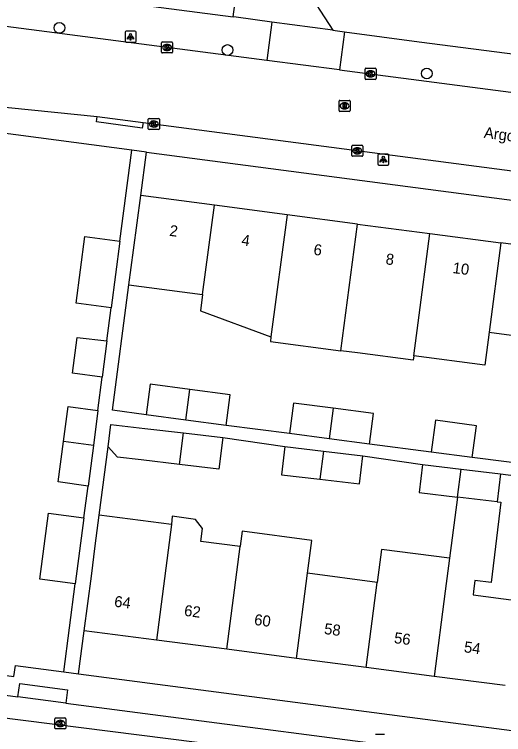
# Model space of a CAD drawing. Extents: x 162186 to 163152, y 385513 to 386513.
# Drawn here: x 162401.2 to 162445.6, y 386262.6 to 386328 of the extents above; entities that cross this region are included whole.
import ezdxf

# ---------------------------------------------------------------- set-up
doc = ezdxf.new("R2010")
doc.units = 0
for name, color, linetype in [('IMGEO_Boom', 7, 'Continuous'), ('IMGEO_Kolk', 7, 'Continuous'), ('IMGEO_Lichtpunt', 7, 'Continuous'), ('IMGEO_Openbare_ruimte_label', 7, 'Continuous'), ('IMGEO_Pand', 7, 'Continuous'), ('IMGEO_Pand_nummerreeks', 7, 'Continuous'), ('IMGEO_Rijbaan_lokaal_open', 7, 'Continuous'), ('IMGEO_Rioolput', 7, 'Continuous'), ('IMGEO_Voetpad_open', 7, 'Continuous')]:
    doc.layers.add(name, color=color, linetype=linetype)

msp = doc.modelspace()

# ---------------------------------------------------------------- linework, layer by layer
at = {"layer": 'IMGEO_Boom'}
for centre in [(162405.294, 386326.739), (162420.542, 386324.727), (162438.622, 386322.597)]:
    msp.add_circle(centre, 0.489, dxfattribs=at)
at = {"layer": 'IMGEO_Kolk'}
for p, q in [((162414.558, 386324.536), (162414.558, 386325.388)), ((162414.633, 386325.462), (162415.485, 386325.462)), ((162415.559, 386325.388), (162415.559, 386324.536)), ((162415.069, 386324.682), (162415.044, 386324.682)), ((162415.046, 386325.242), (162415.071, 386325.242)), ((162415.485, 386324.462), (162414.633, 386324.462)), ((162433.021, 386322.141), (162433.021, 386322.993)), ((162433.096, 386323.067), (162433.948, 386323.067)), ((162433.509, 386322.847), (162433.534, 386322.847)), ((162434.022, 386322.993), (162434.022, 386322.141)), ((162433.948, 386322.067), (162433.096, 386322.067)), ((162433.532, 386322.287), (162433.507, 386322.287)), ((162413.359, 386317.588), (162413.359, 386318.44)), ((162413.434, 386318.514), (162414.286, 386318.514)), ((162413.847, 386318.294), (162413.872, 386318.294)), ((162414.36, 386318.44), (162414.36, 386317.588)), ((162414.286, 386317.514), (162413.434, 386317.514)), ((162413.87, 386317.734), (162413.845, 386317.734)), ((162431.815, 386315.157), (162431.815, 386316.009)), ((162431.89, 386316.083), (162432.742, 386316.083)), ((162432.303, 386315.863), (162432.328, 386315.863)), ((162432.816, 386316.009), (162432.816, 386315.157)), ((162432.742, 386315.083), (162431.89, 386315.083)), ((162432.326, 386315.303), (162432.301, 386315.303)), ((162404.87, 386263.186), (162404.87, 386264.038)), ((162404.945, 386264.112), (162405.797, 386264.112)), ((162405.358, 386263.892), (162405.383, 386263.892)), ((162405.871, 386264.038), (162405.871, 386263.186)), ((162405.381, 386263.332), (162405.356, 386263.332)), ((162405.797, 386263.112), (162404.945, 386263.112))]:
    msp.add_line(p, q, dxfattribs=at)
for points in [[(162414.558, 386324.536), (162414.558, 386325.388)], [(162414.633, 386325.462), (162415.485, 386325.462)], [(162415.559, 386325.388), (162415.559, 386324.536)], [(162414.879, 386325.162), (162415.002, 386325.162), (162415.002, 386325.011), (162415.132, 386325.162), (162415.296, 386325.162), (162415.15, 386325.011), (162415.303, 386324.762), (162415.151, 386324.762), (162415.066, 386324.926), (162415.002, 386324.859), (162415.002, 386324.762), (162414.879, 386324.762), (162414.879, 386325.162)], [(162415.485, 386324.462), (162414.633, 386324.462)], [(162433.021, 386322.141), (162433.021, 386322.993)], [(162433.096, 386323.067), (162433.948, 386323.067)], [(162433.342, 386322.767), (162433.465, 386322.767), (162433.465, 386322.616), (162433.595, 386322.767), (162433.759, 386322.767), (162433.613, 386322.616), (162433.766, 386322.367), (162433.614, 386322.367), (162433.529, 386322.531), (162433.465, 386322.464), (162433.465, 386322.367), (162433.342, 386322.367), (162433.342, 386322.767)], [(162434.022, 386322.993), (162434.022, 386322.141)], [(162433.948, 386322.067), (162433.096, 386322.067)], [(162413.359, 386317.588), (162413.359, 386318.44)], [(162413.434, 386318.514), (162414.286, 386318.514)], [(162413.68, 386318.214), (162413.803, 386318.214), (162413.803, 386318.063), (162413.933, 386318.214), (162414.097, 386318.214), (162413.951, 386318.063), (162414.104, 386317.814), (162413.952, 386317.814), (162413.867, 386317.978), (162413.803, 386317.911), (162413.803, 386317.814), (162413.68, 386317.814), (162413.68, 386318.214)], [(162414.36, 386318.44), (162414.36, 386317.588)], [(162414.286, 386317.514), (162413.434, 386317.514)], [(162431.815, 386315.157), (162431.815, 386316.009)], [(162431.89, 386316.083), (162432.742, 386316.083)], [(162432.136, 386315.783), (162432.259, 386315.783), (162432.259, 386315.632), (162432.389, 386315.783), (162432.553, 386315.783), (162432.407, 386315.632), (162432.56, 386315.383), (162432.408, 386315.383), (162432.323, 386315.547), (162432.259, 386315.48), (162432.259, 386315.383), (162432.136, 386315.383), (162432.136, 386315.783)], [(162432.816, 386316.009), (162432.816, 386315.157)], [(162432.742, 386315.083), (162431.89, 386315.083)], [(162404.87, 386263.186), (162404.87, 386264.038)], [(162404.945, 386264.112), (162405.797, 386264.112)], [(162405.871, 386264.038), (162405.871, 386263.186)], [(162405.191, 386263.812), (162405.314, 386263.812), (162405.314, 386263.661), (162405.444, 386263.812), (162405.608, 386263.812), (162405.462, 386263.661), (162405.615, 386263.412), (162405.463, 386263.412), (162405.378, 386263.576), (162405.314, 386263.509), (162405.314, 386263.412), (162405.191, 386263.412), (162405.191, 386263.812)], [(162405.797, 386263.112), (162404.945, 386263.112)]]:
    msp.add_lwpolyline(points, dxfattribs=at)
for centre, start, end in [((162414.635, 386325.386), 91.55205, 178.44795), ((162414.635, 386325.386), 91.55205, 178.44795), ((162415.483, 386325.386), 1.55205, 88.44795), ((162415.483, 386325.386), 1.55205, 88.44795), ((162414.635, 386324.538), 181.55205, 268.44795), ((162414.635, 386324.538), 181.55205, 268.44795), ((162415.483, 386324.538), 271.55205, 358.44795), ((162415.483, 386324.538), 271.55205, 358.44795), ((162433.098, 386322.991), 91.55205, 178.44795), ((162433.098, 386322.991), 91.55205, 178.44795), ((162433.946, 386322.991), 1.55205, 88.44795), ((162433.946, 386322.991), 1.55205, 88.44795), ((162433.098, 386322.143), 181.55205, 268.44795), ((162433.098, 386322.143), 181.55205, 268.44795), ((162433.946, 386322.143), 271.55205, 358.44795), ((162433.946, 386322.143), 271.55205, 358.44795), ((162413.436, 386318.438), 91.55205, 178.44795), ((162413.436, 386318.438), 91.55205, 178.44795), ((162414.284, 386318.438), 1.55205, 88.44795), ((162414.284, 386318.438), 1.55205, 88.44795), ((162413.436, 386317.59), 181.55205, 268.44795), ((162413.436, 386317.59), 181.55205, 268.44795), ((162414.284, 386317.59), 271.55205, 358.44795), ((162414.284, 386317.59), 271.55205, 358.44795), ((162431.892, 386316.007), 91.55205, 178.44795), ((162431.892, 386316.007), 91.55205, 178.44795), ((162432.74, 386316.007), 1.55205, 88.44795), ((162432.74, 386316.007), 1.55205, 88.44795), ((162431.892, 386315.159), 181.55205, 268.44795), ((162431.892, 386315.159), 181.55205, 268.44795), ((162432.74, 386315.159), 271.55205, 358.44795), ((162432.74, 386315.159), 271.55205, 358.44795), ((162404.947, 386264.036), 91.55205, 178.44795), ((162404.947, 386264.036), 91.55205, 178.44795), ((162405.795, 386264.036), 1.55205, 88.44795), ((162405.795, 386264.036), 1.55205, 88.44795), ((162404.947, 386263.188), 181.55205, 268.44795), ((162404.947, 386263.188), 181.55205, 268.44795), ((162405.795, 386263.188), 271.55205, 358.44795), ((162405.795, 386263.188), 271.55205, 358.44795)]:
    msp.add_arc(centre, 0.0765, start, end, dxfattribs=at)
for centre, major_axis, ratio, start_param, end_param in [((162415.045, 386324.962), (-0.387, 0.002), 0.722429, 4.712389, 7.853982), ((162415.07, 386324.962), (-0.39, 0.002), 0.717154, 1.570796, 4.712389), ((162433.508, 386322.567), (-0.387, 0.002), 0.722429, 4.712389, 7.853982), ((162433.533, 386322.567), (-0.39, 0.002), 0.717154, 1.570796, 4.712389), ((162413.846, 386318.014), (-0.387, 0.002), 0.722429, 4.712389, 7.853982), ((162413.871, 386318.014), (-0.39, 0.002), 0.717154, 1.570796, 4.712389), ((162432.302, 386315.583), (-0.387, 0.002), 0.722429, 4.712389, 7.853982), ((162432.327, 386315.583), (-0.39, 0.002), 0.717154, 1.570796, 4.712389), ((162405.357, 386263.612), (-0.387, 0.002), 0.722429, 4.712389, 7.853982), ((162405.382, 386263.612), (-0.39, 0.002), 0.717154, 1.570796, 4.712389)]:
    msp.add_ellipse(centre, major_axis=major_axis, ratio=ratio, start_param=start_param, end_param=end_param, dxfattribs=at)
at = {"layer": 'IMGEO_Lichtpunt'}
for p, q in [((162411.248, 386326.344), (162411.248, 386325.537)), ((162411.248, 386326.344), (162411.248, 386325.537)), ((162412.15, 386326.439), (162411.342, 386326.439)), ((162412.15, 386326.439), (162411.342, 386326.439)), ((162412.244, 386325.537), (162412.244, 386326.344)), ((162412.244, 386325.537), (162412.244, 386326.344)), ((162411.342, 386325.443), (162412.15, 386325.443)), ((162411.342, 386325.443), (162412.15, 386325.443)), ((162434.179, 386315.191), (162434.179, 386314.384)), ((162434.179, 386315.191), (162434.179, 386314.384)), ((162435.081, 386315.286), (162434.273, 386315.286)), ((162435.081, 386315.286), (162434.273, 386315.286)), ((162435.175, 386314.384), (162435.175, 386315.191)), ((162435.175, 386314.384), (162435.175, 386315.191)), ((162434.273, 386314.29), (162435.081, 386314.29)), ((162434.273, 386314.29), (162435.081, 386314.29)), ((162434.777, 386262.594), (162433.969, 386262.594)), ((162434.777, 386262.594), (162433.969, 386262.594))]:
    msp.add_line(p, q, dxfattribs=at)
for points in [[(162411.622, 386326.008), (162411.661, 386325.98), (162411.473, 386325.718), (162411.435, 386325.745), (162411.622, 386326.008)], [(162411.834, 386325.98), (162411.872, 386326.007), (162412.059, 386325.745), (162412.02, 386325.717), (162411.834, 386325.98)], [(162411.724, 386325.96), (162411.771, 386325.96), (162411.771, 386325.638), (162411.724, 386325.638), (162411.724, 386325.96)], [(162434.553, 386314.855), (162434.592, 386314.827), (162434.404, 386314.565), (162434.366, 386314.592), (162434.553, 386314.855)], [(162434.655, 386314.807), (162434.702, 386314.807), (162434.702, 386314.485), (162434.655, 386314.485), (162434.655, 386314.807)], [(162434.765, 386314.827), (162434.803, 386314.854), (162434.99, 386314.592), (162434.951, 386314.564), (162434.765, 386314.827)]]:
    msp.add_lwpolyline(points, dxfattribs=at)
for centre in [(162411.747, 386326.142), (162434.678, 386314.989)]:
    msp.add_circle(centre, 0.0994, dxfattribs=at)
for centre, start, end in [((162411.342, 386326.344), 90, 180), ((162411.342, 386326.344), 90, 180), ((162412.15, 386326.344), 0, 90), ((162412.15, 386326.344), 0, 90), ((162411.342, 386325.537), 180, 270), ((162411.342, 386325.537), 180, 270), ((162412.15, 386325.537), 270, 0), ((162412.15, 386325.537), 270, 360), ((162434.273, 386315.191), 90, 180), ((162434.273, 386315.191), 90, 180), ((162435.081, 386315.191), 0, 90), ((162435.081, 386315.191), 0, 90), ((162434.273, 386314.384), 180, 270), ((162434.273, 386314.384), 180, 270), ((162435.081, 386314.384), 270, 0), ((162435.081, 386314.384), 270, 360)]:
    msp.add_arc(centre, 0.0946, start, end, dxfattribs=at)
at = {"layer": 'IMGEO_Pand'}
for points in [[(162411.6, 386303.411), (162412.014, 386306.559), (162412.666, 386311.516)], [(162419.348, 386310.637), (162412.666, 386311.516)], [(162418.277, 386302.533), (162419.348, 386310.637)], [(162425.952, 386309.769), (162419.348, 386310.637)], [(162425.952, 386309.769), (162424.488, 386298.691)], [(162432.348, 386308.928), (162425.952, 386309.769)], [(162430.828, 386297.428), (162432.348, 386308.928)], [(162432.348, 386308.928), (162438.913, 386308.065)], [(162409.987, 386301.337), (162406.812, 386301.752), (162407.604, 386307.798), (162410.778, 386307.382)], [(162437.447, 386296.964), (162437.843, 386299.96), (162438.913, 386308.065)], [(162438.913, 386308.065), (162445.352, 386307.218)], [(162410.778, 386307.382), (162409.987, 386301.337)], [(162444.281, 386299.114), (162450.818, 386298.254), (162451.232, 386301.402), (162451.884, 386306.359), (162445.352, 386307.218)], [(162445.352, 386307.218), (162444.281, 386299.114)], [(162411.6, 386303.411), (162418.277, 386302.533)], [(162418.277, 386302.533), (162418.081, 386301.046), (162424.488, 386298.691)], [(162409.173, 386295.045), (162406.47, 386295.405), (162406.891, 386298.649), (162409.598, 386298.333)], [(162424.488, 386298.691), (162424.432, 386298.269), (162430.828, 386297.428)], [(162444.281, 386299.114), (162443.887, 386296.117), (162437.447, 386296.964)], [(162409.598, 386298.333), (162409.173, 386295.045)], [(162437.447, 386296.964), (162437.394, 386296.564), (162432.332, 386297.23), (162430.828, 386297.428)], [(162417.139, 386293.919), (162413.538, 386294.395), (162413.171, 386291.621)], [(162416.772, 386291.144), (162417.139, 386293.919)], [(162420.413, 386290.663), (162420.78, 386293.438), (162417.139, 386293.919)], [(162430.139, 386292.21), (162426.538, 386292.686), (162426.171, 386289.912)], [(162405.664, 386289.203), (162406.077, 386292.377), (162408.783, 386292.025)], [(162408.783, 386292.025), (162408.371, 386288.843)], [(162430.139, 386292.21), (162429.772, 386289.435)], [(162433.413, 386288.954), (162433.78, 386291.729), (162430.139, 386292.21)], [(162416.772, 386291.144), (162413.171, 386291.621)], [(162409.724, 386288.701), (162409.963, 386290.746), (162413.039, 386290.386), (162416.538, 386289.976)], [(162420.413, 386290.663), (162416.772, 386291.144)], [(162442.728, 386287.736), (162443.118, 386290.625), (162439.415, 386291.125), (162439.025, 386288.235)], [(162416.202, 386287.109), (162416.538, 386289.976)], [(162420.105, 386289.558), (162419.758, 386286.692), (162416.202, 386287.109)], [(162416.538, 386289.976), (162420.105, 386289.558)], [(162429.772, 386289.435), (162426.171, 386289.912)], [(162433.413, 386288.954), (162429.772, 386289.435)], [(162407.893, 386285.145), (162405.188, 386285.542), (162405.664, 386289.203)], [(162408.371, 386288.843), (162405.664, 386289.203)], [(162408.371, 386288.843), (162407.893, 386285.145)], [(162425.751, 386288.729), (162425.452, 386286.183), (162428.917, 386285.777)], [(162425.751, 386288.729), (162429.247, 386288.319)], [(162416.202, 386287.109), (162412.703, 386287.519), (162410.576, 386287.768), (162409.724, 386288.701)], [(162429.247, 386288.319), (162428.917, 386285.777)], [(162429.247, 386288.319), (162432.817, 386287.901)], [(162442.728, 386287.736), (162439.025, 386288.235)], [(162428.917, 386285.777), (162432.518, 386285.356), (162432.817, 386287.901)], [(162438.244, 386287.101), (162437.945, 386284.555), (162441.412, 386284.149)], [(162438.244, 386287.101), (162441.743, 386286.691)], [(162441.412, 386284.149), (162441.743, 386286.691)], [(162441.743, 386286.691), (162445.31, 386286.273)], [(162445.31, 386286.273), (162445.011, 386283.728)], [(162441.412, 386284.149), (162440.691, 386278.599)], [(162445.011, 386283.728), (162441.412, 386284.149)], [(162445.011, 386283.728), (162445.328, 386283.691), (162444.477, 386276.412), (162442.98, 386276.587), (162442.861, 386275.571), (162442.827, 386275.274), (162446.744, 386274.763)], [(162406.736, 386276.277), (162403.525, 386276.697), (162404.31, 386282.7), (162407.522, 386282.28)], [(162407.522, 386282.28), (162406.736, 386276.277)], [(162407.543, 386272.02), (162408.189, 386276.979), (162408.549, 386279.741), (162408.909, 386282.51)], [(162415.456, 386281.658), (162408.909, 386282.51)], [(162421.686, 386279.661), (162418.116, 386280.125), (162418.268, 386281.292), (162417.644, 386282.131), (162415.533, 386282.406), (162415.456, 386281.658)], [(162415.456, 386281.658), (162414.092, 386271.167)], [(162427.807, 386277.231), (162428.197, 386280.224), (162421.866, 386281.047), (162421.691, 386279.701), (162421.686, 386279.661)], [(162420.473, 386270.335), (162421.686, 386279.661)], [(162440.691, 386278.599), (162434.502, 386279.404), (162434.113, 386276.409)], [(162440.691, 386278.599), (162440.301, 386275.603), (162439.297, 386267.882)], [(162426.804, 386269.51), (162427.807, 386277.231)], [(162434.113, 386276.409), (162427.807, 386277.231)], [(162433.109, 386268.688), (162434.113, 386276.409)], [(162414.092, 386271.167), (162407.543, 386272.02)], [(162420.473, 386270.335), (162414.092, 386271.167)], [(162426.804, 386269.51), (162420.473, 386270.335)], [(162433.109, 386268.688), (162426.804, 386269.51)], [(162439.297, 386267.882), (162433.109, 386268.688)], [(162445.74, 386267.042), (162439.297, 386267.882)]]:
    msp.add_lwpolyline(points, dxfattribs=at)
at = {"layer": 'IMGEO_Rijbaan_lokaal_open'}
for points in [[(162421.056, 386327.743), (162422.411, 386337.803)], [(162428.393, 386337.372), (162427.473, 386330.612), (162430.094, 386326.523)], [(162424.113, 386323.778), (162398.306, 386327.127), (162394.765, 386327.647)], [(162424.569, 386327.27), (162421.334, 386327.707), (162421.056, 386327.743)], [(162430.094, 386326.523), (162424.569, 386327.27)], [(162430.717, 386322.917), (162424.113, 386323.778)], [(162430.717, 386322.917), (162499.627, 386313.936), (162500, 386313.887), (162505.895, 386313.114), (162551.376, 386307.147), (162557.5, 386306.343), (162586.759, 386302.71), (162592.437, 386301.969), (162597.633, 386301.29), (162608.171, 386299.914), (162608.395, 386299.882)], [(162393.671, 386320.383), (162398.862, 386319.696), (162408.726, 386318.7)], [(162408.726, 386318.7), (162412.877, 386318.155)], [(162412.877, 386318.155), (162452.611, 386312.938)], [(162448.882, 386257.938), (162386.418, 386265.855)]]:
    msp.add_lwpolyline(points, dxfattribs=at)
at = {"layer": 'IMGEO_Rioolput'}
for p, q in [((162430.74, 386320.158), (162431.592, 386320.158)), ((162430.665, 386319.232), (162430.665, 386320.084)), ((162431.153, 386319.938), (162431.178, 386319.938)), ((162431.666, 386320.084), (162431.666, 386319.232)), ((162431.592, 386319.158), (162430.74, 386319.158)), ((162431.176, 386319.378), (162431.151, 386319.378))]:
    msp.add_line(p, q, dxfattribs=at)
for points in [[(162430.74, 386320.158), (162431.592, 386320.158)], [(162430.665, 386319.232), (162430.665, 386320.084)], [(162431.254, 386319.856), (162431.002, 386319.858), (162431.002, 386319.458)], [(162431.002, 386319.458), (162431.126, 386319.458), (162431.126, 386319.62), (162431.137, 386319.62)], [(162431.18, 386319.777), (162431.126, 386319.777), (162431.126, 386319.696)], [(162431.126, 386319.696), (162431.178, 386319.696)], [(162431.184, 386319.591), (162431.255, 386319.458), (162431.395, 386319.458), (162431.33, 386319.584)], [(162431.666, 386320.084), (162431.666, 386319.232)], [(162431.592, 386319.158), (162430.74, 386319.158)]]:
    msp.add_lwpolyline(points, dxfattribs=at)
for centre, radius, start, end in [((162430.742, 386320.082), 0.0765, 91.55205, 178.44795), ((162430.742, 386320.082), 0.0765, 91.55205, 178.44795), ((162431.59, 386320.082), 0.0765, 1.55205, 88.44795), ((162431.59, 386320.082), 0.0765, 1.55205, 88.44795), ((162431.136, 386319.567), 0.0533, 26.02933, 88.69889), ((162431.162, 386319.885), 0.19, 274.7715, 282.96867), ((162431.186, 386319.681), 0.0964, 77.00612, 93.18647), ((162431.2, 386319.738), 0.0378, 276.66336, 79.67722), ((162431.253, 386319.746), 0.109, 350.36119, 89.41601), ((162431.251, 386319.746), 0.112, 277.58423, 350.98172), ((162431.235, 386319.531), 0.108, 29.51342, 73.79051), ((162430.742, 386319.234), 0.0765, 181.55205, 268.44795), ((162430.742, 386319.234), 0.0765, 181.55205, 268.44795), ((162431.59, 386319.234), 0.0765, 271.55205, 358.44795), ((162431.59, 386319.234), 0.0765, 271.55205, 358.44795)]:
    msp.add_arc(centre, radius, start, end, dxfattribs=at)
for centre, major_axis, ratio, start_param, end_param in [((162431.152, 386319.658), (-0.387, 0.002), 0.722429, 4.712389, 7.853982), ((162431.177, 386319.658), (-0.39, 0.002), 0.717154, 1.570796, 4.712389)]:
    msp.add_ellipse(centre, major_axis=major_axis, ratio=ratio, start_param=start_param, end_param=end_param, dxfattribs=at)
at = {"layer": 'IMGEO_Voetpad_open'}
for points in [[(162412.905, 386328.806), (162421.056, 386327.743)], [(162424.569, 386327.27), (162424.113, 386323.778)], [(162430.094, 386326.523), (162430.305, 386326.495), (162431.169, 386326.378)], [(162431.169, 386326.378), (162430.717, 386322.917)], [(162431.169, 386326.378), (162437.933, 386325.465), (162491.222, 386318.605), (162495.408, 386318.031), (162500, 386317.441), (162505.38, 386316.75), (162509.176, 386316.263), (162550.981, 386310.895), (162592.901, 386305.371), (162598.062, 386304.691), (162608.854, 386303.164)], [(162411.863, 386315.638), (162392.843, 386318.138), (162392.559, 386318.162), (162392.275, 386318.161), (162391.991, 386318.135), (162391.711, 386318.083), (162391.437, 386318.007), (162391.171, 386317.906), (162390.915, 386317.782), (162390.671, 386317.635), (162390.441, 386317.468), (162390.227, 386317.28), (162390.03, 386317.074), (162389.853, 386316.852), (162389.696, 386316.614), (162389.561, 386316.363), (162389.449, 386316.102), (162389.361, 386315.831), (162389.298, 386315.554), (162389.272, 386315.389)], [(162412.877, 386318.155), (162412.805, 386317.651), (162408.654, 386318.198), (162408.726, 386318.7)], [(162410.778, 386307.382), (162411.863, 386315.638)], [(162413.185, 386315.464), (162411.863, 386315.638)], [(162412.666, 386311.516), (162413.185, 386315.464)], [(162413.185, 386315.464), (162500, 386304.056), (162543.349, 386298.36)], [(162413.171, 386291.621), (162410.103, 386292.027), (162411.6, 386303.411)], [(162409.598, 386298.333), (162409.987, 386301.337)], [(162408.783, 386292.025), (162409.173, 386295.045)], [(162426.171, 386289.912), (162420.413, 386290.663)], [(162420.105, 386289.558), (162425.751, 386288.729)], [(162439.025, 386288.235), (162433.413, 386288.954)], [(162408.909, 386282.51), (162409.724, 386288.701)], [(162432.817, 386287.901), (162438.244, 386287.101)], [(162449.199, 386286.942), (162442.728, 386287.736)], [(162445.31, 386286.273), (162473.322, 386282.619)], [(162407.522, 386282.28), (162407.893, 386285.145)], [(162405.69, 386268.292), (162406.736, 386276.277)], [(162407.034, 386268.116), (162407.543, 386272.02)], [(162386.179, 386269.874), (162401.168, 386267.882), (162401.299, 386268.868), (162405.69, 386268.292)], [(162405.69, 386268.292), (162407.034, 386268.116)], [(162407.034, 386268.116), (162500, 386255.941), (162516.96, 386253.72)], [(162389.937, 386267.559), (162401.526, 386266.019)], [(162401.526, 386266.019), (162401.699, 386267.241), (162406.025, 386266.672), (162405.863, 386265.443)], [(162405.863, 386265.443), (162401.526, 386266.019)], [(162405.863, 386265.443), (162445.81, 386260.241), (162446.232, 386260.105), (162446.358, 386260.037), (162446.458, 386259.984), (162446.794, 386259.589), (162447.449, 386258.809)]]:
    msp.add_lwpolyline(points, dxfattribs=at)

# ---------------------------------------------------------------- texts
at = {"layer": 'IMGEO_Openbare_ruimte_label'}
msp.add_text('Argostraat', height=1, rotation=352.52658, dxfattribs=at).set_placement((162443.766, 386316.77))
at = {"layer": 'IMGEO_Pand_nummerreeks'}
for s, rotation, p in [('2', 352.50883, (162415.232, 386307.87)), ('4', 352.50883, (162421.77, 386307.011)), ('6', 352.50882, (162428.307, 386306.151)), ('8', 352.51144, (162434.847, 386305.292)), ('10', 352.51144, (162440.925, 386304.492)), ('64', 352.57507, (162410.223, 386274.212)), ('62', 352.57447, (162416.567, 386273.385)), ('60', 352.57447, (162422.92, 386272.557)), ('58', 352.57508, (162429.266, 386271.73)), ('56', 352.57508, (162435.61, 386270.904)), ('54', 352.57447, (162441.957, 386270.077))]:
    msp.add_text(s, height=1, rotation=rotation, dxfattribs=at).set_placement(p)

doc.saveas('drawing.dxf')
